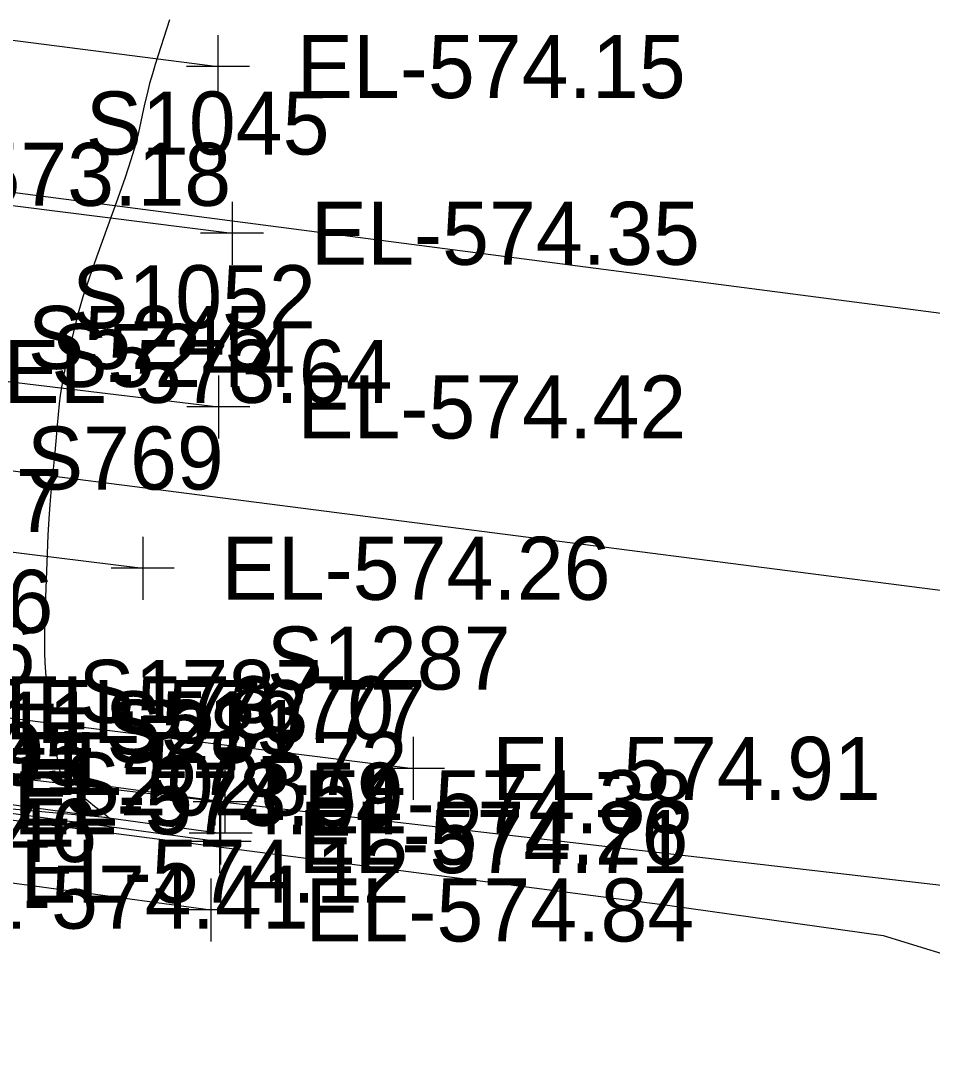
# Model space of a CAD drawing. Extents: x 1724534 to 1727318, y 657156 to 660047.
# Drawn here: x 1725903.6 to 1725961.5, y 658518.4 to 658583.4 of the extents above; entities that cross this region are included whole.
import ezdxf

# ---------------------------------------------------------------- set-up
doc = ezdxf.new("R2010")
doc.units = 0
for name, color, linetype in [('SURVEY - CONTOURS - Intermediate with optional Text', 7, 'Continuous'), ('SURVEY - DRAINAGE - Storm Sewer', 7, 'Continuous'), ('SURVEY - DRAINAGE - Storm Sewer - Points - Numbers', 7, 'Continuous'), ('SURVEY - DTM - Breaklines', 7, 'Continuous'), ('SURVEY - DTM - Breaklines - Points - Elevations', 7, 'Continuous'), ('SURVEY - DTM - Breaklines - Points - Locators', 7, 'Continuous'), ('SURVEY - DTM - Breaklines - Points - Numbers', 7, 'Continuous'), ('SURVEY - TRAFFIC CONTROL - Pavement Marking - Points - Elevations', 7, 'Continuous'), ('SURVEY - TRAFFIC CONTROL - Pavement Marking - Points - Locators', 7, 'Continuous'), ('SURVEY - TRAFFIC CONTROL - Pavement Marking - Points - Numbers', 7, 'Continuous'), ('SURVEY - TRAFFIC CONTROL - Pavement Marking with Text', 7, 'Continuous'), ('SURVEY - TRAFFIC CONTROL - Signs - Points - Elevations', 7, 'Continuous'), ('SURVEY - TRANSPORTATION - Features', 7, 'Continuous'), ('SURVEY - TRANSPORTATION - Features - Points - Elevations', 7, 'Continuous'), ('SURVEY - TRANSPORTATION - Features - Points - Locators', 7, 'Continuous'), ('SURVEY - TRANSPORTATION - Features - Points - Numbers', 7, 'Continuous'), ('SURVEY - TRANSPORTATION - Roads', 7, 'Continuous'), ('SURVEY - TRANSPORTATION - Roads - Points - Elevations', 7, 'Continuous'), ('SURVEY - TRANSPORTATION - Roads - Points - Locators', 7, 'Continuous'), ('SURVEY - TRANSPORTATION - Roads - Points - Numbers', 7, 'Continuous'), ('SURVEY - UTILITIES - Electric (Underground) with Text', 7, 'Continuous'), ('SURVEY - UTILITIES - Water with Text', 7, 'Continuous')]:
    doc.layers.add(name, color=color, linetype=linetype)

msp = doc.modelspace()

# ---------------------------------------------------------------- linework, layer by layer
at = {"layer": 'SURVEY - CONTOURS - Intermediate with optional Text'}
msp.add_lwpolyline([(1725913.078, 658583.42), (1725912.174, 658580.602), (1725911.991, 658580.005), (1725911.818, 658579.385), (1725911.656, 658578.741), (1725911.504, 658578.075), (1725911.111, 658576.269), (1725910.918, 658575.5), (1725910.636, 658574.55), (1725910.262, 658573.419), (1725909.799, 658572.105), (1725908.441, 658568.361), (1725907.972, 658567.03), (1725907.584, 658565.844), (1725907.275, 658564.803), (1725907.047, 658563.908), (1725906.544, 658561.715), (1725906.374, 658560.932), (1725906.239, 658560.228), (1725906.141, 658559.603), (1725906.079, 658559.056), (1725905.962, 658557.704), (1725905.915, 658557.173), (1725905.801, 658555.968), (1725905.549, 658553.434), (1725905.482, 658552.668), (1725905.421, 658551.765), (1725905.365, 658550.726), (1725905.315, 658549.55), (1725905.189, 658546.232), (1725905.153, 658545.073), (1725905.138, 658544.084), (1725905.146, 658543.266), (1725905.175, 658542.619), (1725905.45, 658538.793), (1725905.641, 658538.04), (1725905.686, 658537.852), (1725905.74, 658537.609), (1725905.802, 658537.312), (1725906.218, 658535.191), (1725906.933, 658534.646), (1725907.236, 658534.406), (1725908.326, 658533.526), (1725908.846, 658533.113), (1725908.98, 658533.003), (1725909.252, 658532.774), (1725908.322, 658532.858), (1725908.041, 658532.883), (1725903.802, 658533.268), (1725901.902, 658533.441)], dxfattribs=at)
at = {"layer": 'SURVEY - DRAINAGE - Storm Sewer'}
for p, q in [((1725900.583, 658555.127), (1726009.35, 658541.146)), ((1725877.563, 658538.288), (1726031.356, 658520.458))]:
    msp.add_line(p, q, dxfattribs=at)
at = {"layer": 'SURVEY - DTM - Breaklines'}
msp.add_lwpolyline([(1725680.682, 658560.757), (1725700.532, 658558.327), (1725720.383, 658555.896), (1725740.231, 658553.451), (1725761.261, 658550.794), (1725763.358, 658550.522), (1725772.397, 658549.361), (1725785.767, 658547.812), (1725794.485, 658546.715), (1725814.329, 658544.278), (1725834.171, 658541.836), (1725838.432, 658541.293), (1725858.267, 658538.797), (1725873.4, 658536.913), (1725878.358, 658536.288), (1725898.186, 658533.731), (1725916.254, 658531.264)], dxfattribs=at)
at = {"layer": 'SURVEY - DTM - Breaklines - Points - Locators'}
for p, q in [((1725916.254, 658533.264), (1725916.254, 658529.264)), ((1725918.254, 658531.264), (1725914.254, 658531.264))]:
    msp.add_line(p, q, dxfattribs=at)
at = {"layer": 'SURVEY - TRAFFIC CONTROL - Pavement Marking - Points - Locators'}
for p, q in [((1725916.153, 658582.463), (1725916.153, 658578.463)), ((1725918.153, 658580.463), (1725914.153, 658580.463)), ((1725917.054, 658571.88), (1725917.054, 658567.88)), ((1725919.054, 658569.88), (1725915.054, 658569.88)), ((1725916.187, 658560.855), (1725916.187, 658556.855)), ((1725918.187, 658558.855), (1725914.187, 658558.855)), ((1725911.384, 658550.615), (1725911.384, 658546.615)), ((1725913.384, 658548.615), (1725909.384, 658548.615))]:
    msp.add_line(p, q, dxfattribs=at)
at = {"layer": 'SURVEY - TRAFFIC CONTROL - Pavement Marking with Text'}
for points in [[(1725469.93, 658636.195), (1725476.311, 658635.371), (1725478.295, 658635.122), (1725516.011, 658630.481), (1725599.369, 658620.164), (1725678.757, 658610.338), (1725738.298, 658602.97), (1725780.716, 658597.719), (1725790.639, 658596.491), (1725852.127, 658588.674), (1725871.961, 658586.151), (1725916.153, 658580.463)], [(1725507.893, 658598.435), (1725611.44, 658585.624), (1725663.045, 658579.239), (1725732.511, 658570.646), (1725771.433, 658565.831), (1725828.993, 658558.789), (1725876.604, 658552.91), (1725911.384, 658548.615)], [(1725691.276, 658598.614), (1725717.028, 658595.036), (1725719.009, 658594.766), (1725742.941, 658591.917), (1725766.76, 658588.985), (1725807.969, 658583.629), (1725837.716, 658579.798), (1725859.541, 658577.092), (1725887.31, 658573.624), (1725917.054, 658569.88)], [(1725753.893, 658578.677), (1725768.555, 658576.886), (1725792.375, 658573.977), (1725838.021, 658568.345), (1725840.005, 658568.1), (1725897.548, 658561.116), (1725916.187, 658558.855)]]:
    msp.add_lwpolyline(points, dxfattribs=at)
at = {"layer": 'SURVEY - TRANSPORTATION - Features'}
for points in [[(1725680.75, 658561.297), (1725700.601, 658558.867), (1725720.452, 658556.439), (1725740.3, 658553.994), (1725761.33, 658551.338), (1725763.427, 658551.066), (1725772.465, 658549.905), (1725773.017, 658549.841), (1725785.837, 658548.356), (1725794.555, 658547.258), (1725814.399, 658544.822), (1725834.241, 658542.379), (1725838.502, 658541.836), (1725858.338, 658539.34), (1725873.47, 658537.457), (1725878.428, 658536.831), (1725898.256, 658534.275), (1725916.324, 658531.808)], [(1725773.017, 658549.841), (1725772.713, 658551.857), (1725786.089, 658550.308), (1725794.807, 658549.211), (1725814.651, 658546.773), (1725834.493, 658544.331), (1725838.754, 658543.788), (1725858.589, 658541.292), (1725873.721, 658539.408), (1725878.681, 658538.783), (1725898.508, 658536.226), (1725916.581, 658533.801)], [(1725760.676, 658546.181), (1725762.959, 658547.374), (1725771.996, 658546.202), (1725785.261, 658543.884), (1725793.979, 658542.787), (1725813.816, 658540.298), (1725833.635, 658537.675), (1725837.876, 658536.979), (1725857.711, 658534.482), (1725872.844, 658532.599), (1725877.802, 658531.973), (1725897.627, 658529.389), (1725915.695, 658526.927)]]:
    msp.add_lwpolyline(points, dxfattribs=at)
at = {"layer": 'SURVEY - TRANSPORTATION - Features - Points - Locators'}
for p, q in [((1725916.581, 658535.801), (1725916.581, 658531.801)), ((1725918.581, 658533.801), (1725914.581, 658533.801)), ((1725916.324, 658533.808), (1725916.324, 658529.808)), ((1725918.324, 658531.808), (1725914.324, 658531.808)), ((1725915.695, 658528.927), (1725915.695, 658524.927)), ((1725917.695, 658526.927), (1725913.695, 658526.927))]:
    msp.add_line(p, q, dxfattribs=at)
at = {"layer": 'SURVEY - TRANSPORTATION - Roads'}
msp.add_lwpolyline([(1725616.971, 658574.343), (1725730.092, 658560.27), (1725772.626, 658554.978), (1725818.273, 658549.383), (1725869.87, 658543.106), (1725897.655, 658539.757), (1725899.639, 658539.517), (1725928.541, 658535.917)], dxfattribs=at)
at = {"layer": 'SURVEY - TRANSPORTATION - Roads - Points - Locators'}
for p, q in [((1725928.541, 658537.917), (1725928.541, 658533.917)), ((1725930.541, 658535.917), (1725926.541, 658535.917))]:
    msp.add_line(p, q, dxfattribs=at)
at = {"layer": 'SURVEY - UTILITIES - Electric (Underground) with Text'}
msp.add_lwpolyline([(1725780.974, 658547.452), (1725837.588, 658541.08), (1725892.762, 658533.99), (1725944.681, 658527.231), (1725958.361, 658525.297), (1725964.566, 658523.411), (1725971.45, 658518.072), (1725975.975, 658512.132)], dxfattribs=at)
at = {"layer": 'SURVEY - UTILITIES - Water with Text'}
msp.add_lwpolyline([(1725847.724, 658579.712), (1725982.184, 658562.183), (1725988.335, 658559.963), (1726011.571, 658556.88)], dxfattribs=at)

# ---------------------------------------------------------------- texts
at = {"layer": 'SURVEY - DRAINAGE - Storm Sewer - Points - Numbers'}
for s, p in [('S5245', (1725904.095, 658561.269)), ('S5244', (1725905.583, 658560.127))]:
    msp.add_text(s, height=4, dxfattribs=at).set_placement(p)
at = {"layer": 'SURVEY - DTM - Breaklines - Points - Elevations'}
for s, p in [('EL-573.41', (1725883.358, 658534.288)), ('EL-574.04', (1725903.186, 658531.731)), ('EL-574.71', (1725921.254, 658529.264))]:
    msp.add_text(s, height=4, dxfattribs=at).set_placement(p)
at = {"layer": 'SURVEY - DTM - Breaklines - Points - Numbers'}
msp.add_text('S281', height=4, dxfattribs=at).set_placement((1725909.076, 658536.264))
at = {"layer": 'SURVEY - TRAFFIC CONTROL - Pavement Marking - Points - Elevations'}
for s, p in [('EL-574.15', (1725921.153, 658578.463)), ('EL-573.18', (1725892.31, 658571.624)), ('EL-574.35', (1725922.054, 658567.88)), ('EL-573.64', (1725902.548, 658559.116)), ('EL-574.42', (1725921.187, 658556.855)), ('EL-572.87', (1725881.604, 658550.91)), ('EL-574.26', (1725916.384, 658546.615))]:
    msp.add_text(s, height=4, dxfattribs=at).set_placement(p)
at = {"layer": 'SURVEY - TRAFFIC CONTROL - Pavement Marking - Points - Numbers'}
for s, p in [('S1045', (1725907.766, 658574.88)), ('S1052', (1725906.899, 658563.855)), ('S769', (1725904.032, 658553.615))]:
    msp.add_text(s, height=4, dxfattribs=at).set_placement(p)
at = {"layer": 'SURVEY - TRAFFIC CONTROL - Signs - Points - Elevations'}
msp.add_text('EL-574.41', height=4, dxfattribs=at).set_placement((1725897.236, 658525.742))
at = {"layer": 'SURVEY - TRANSPORTATION - Features - Points - Elevations'}
for s, p in [('EL-573.11', (1725883.681, 658536.783)), ('EL-572.95', (1725883.428, 658534.831)), ('EL-573.72', (1725903.508, 658534.226)), ('EL-573.59', (1725903.256, 658532.275)), ('EL-574.38', (1725921.581, 658531.801)), ('EL-573.46', (1725883.802, 658529.973)), ('EL-574.26', (1725921.324, 658529.808)), ('EL-574.12', (1725903.627, 658527.389)), ('EL-574.84', (1725921.695, 658524.927))]:
    msp.add_text(s, height=4, dxfattribs=at).set_placement(p)
at = {"layer": 'SURVEY - TRANSPORTATION - Features - Points - Numbers'}
for s, p in [('S1786', (1725889.11, 658541.226)), ('S1787', (1725907.293, 658538.801)), ('S519', (1725908.972, 658536.808)), ('S2028', (1725906.36, 658532.927))]:
    msp.add_text(s, height=4, dxfattribs=at).set_placement(p)
at = {"layer": 'SURVEY - TRANSPORTATION - Roads - Points - Elevations'}
for s, p in [('EL-573.70', (1725902.655, 658537.757)), ('EL-573.77', (1725904.639, 658537.517)), ('EL-574.91', (1725933.541, 658533.917))]:
    msp.add_text(s, height=4, dxfattribs=at).set_placement(p)
at = {"layer": 'SURVEY - TRANSPORTATION - Roads - Points - Numbers'}
for s, p in [('S1286', (1725890.241, 658544.517)), ('S1287', (1725919.253, 658540.917))]:
    msp.add_text(s, height=4, dxfattribs=at).set_placement(p)

doc.saveas('drawing.dxf')
